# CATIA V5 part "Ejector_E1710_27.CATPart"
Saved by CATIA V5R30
Part number: Vyhazovac_7x160_4
Nomenclature: E1710/7x160
Description: MEUSBURGER
Property "Material": "1.221"
Publications: "__DrillHole", "Base"
Bounding box of the stored display mesh (mm): x -5.992 to 5.992, y -5.992 to 5.992, z 0 to 152
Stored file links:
  E:\Bakalarka\Model\Forma_v7\Ejector_E1710_27.CATPart
  E:\dev\MoldDesign\intel_a\startup\components\MoldCatalog\Ejector\Meusburger\Ejector_E1710\TableE1710.txt
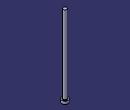
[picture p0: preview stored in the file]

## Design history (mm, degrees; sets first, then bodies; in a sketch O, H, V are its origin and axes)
Parameters
  Ref = "E1710/7x160" {design table}
  D1 = 7 mm {design table}
  D3 = 12 mm {design table}
  L = 160 mm {design table}
  L3 = 5 mm {design table}
  R = 0.5 mm {design table}
  k_d3 = 13 mm {design table}
  k_d1 = 7.2 mm {design table}
  k_F = 0.5 mm {design table}
  kl = 17 mm {design table}
  Mat = "1.221" {design table}
  HeatTreat = "ISO6751" {design table}
  Offset_Parting = 10 mm
  Anti_Rotation = "Normal"
  Anti_Rotation_D = 4 mm
  Anti_Rotation_D_Icut = 4 mm
  Add_Length_L = 1.3377 mm
  Add_Length_D3 = 0 mm
  SupplierRef = "Meusburger 2017"
  BmpRef = "F_MldEjectorD1"
  DrillHole_Length = 225 mm
  ValidationTest = false
  Anti_Rotation_D_min = 4 mm {= OffSet_D1 /2}
  Anti_Rotation_D_max = 5.925 mm {= D3/2-0.075mm}
  Anti_Rotation_D_ref = 4 mm {= Anti_Rotation_D}
  Anti_Rotation_D_Icut_ref = 4 mm {= Anti_Rotation_D_Icut}
  Anti_Rotation_Ref_Icut = 2.3246 mm
  Offset_L = 20 mm
  D = 7 mm {= D1}
  OffSet_D1 = 8 mm {= D1+2*R}
  OffSet_D3 = 13 mm {= D3+1mm}
  XG_Split = -45 mm
  YG_Split = -10 mm
  ZG_Split = -198 mm
  DirX_Split = 0 mm
  DirY_Split = 0 mm
  DirZ_Split = 1 mm
Set1 "BaseBody"
  Point1 "Base": (0, 0, 0)
  Plane1: type Offset, RefPlane xy-plane, Offset 225 {= DrillHole_Length}, reversed
  Sketch1 "Sketch.2" on xy-plane, origin (0, 0, 0), H (1, 0, 0), V (0, 1, 0)
    point P1 (-0.46, 1.1623)
    point P2 (0.46, 1.1623)
    construction line L1 (-0.46, 1.1623) -> (0.46, 1.1623)
    point P3 (0.46, -1.1623)
    line L2 (0.46, -1.1623) -> (0.46, 1.1623)
    point P4 (-0.46, -1.1623)
    construction line L3 (0.46, -1.1623) -> (-0.46, -1.1623)
    line L4 (-0.46, 1.1623) -> (-0.46, -1.1623)
    point P5 (-0.21, 1.1623)
    arc A1 centre (-0.21, 1.1623) radius 0.25 from (-0.21, 1.4123) to (-0.46, 1.1623) ccw
    point P7 (0.21, 1.1623)
    point P8 (0.21, 1.4123)
    arc A2 centre (0.21, 1.1623) radius 0.25 from (0.46, 1.1623) to (0.21, 1.4123) ccw
    line L5 (-0.21, 1.4123) -> (0.21, 1.4123)
    point P9 (-0.46, -1.1623)
    arc A3 centre (-0.21, -1.1623) radius 0.25 from (-0.46, -1.1623) to (-0.21, -1.4123) ccw
    point P11 (0.21, -1.4123)
    line L6 (-0.21, -1.4123) -> (0.21, -1.4123)
    point P12 (0.46, -1.1623)
    arc A4 centre (0.21, -1.1623) radius 0.25 from (0.21, -1.4123) to (0.46, -1.1623) ccw
    point P14 (-0.46, 1.1623)
    point P15 (-0.46, -1.1623)
    point P16 (0.46, 1.1623)
    point P17 (0.46, -1.1623)
    reference projected circle E1 centre (0, 0) radius 1.25 from edge [face of Shaft1 from Sketch2.L3 | face of Shaft1 from Sketch2.L4]
    reference projected circle E2 centre (0, 0) radius 1.25 from edge [face of Shaft1 from Sketch2.L3 | face of Shaft1 from Sketch2.L4]
    reference projected circle E3 centre (0, 0) radius 1.25 from edge [face of Shaft1 from Sketch2.L3 | face of Shaft1 from Sketch2.L4]
    reference projected circle E4 centre (0, 0) radius 1.25 from edge [face of Shaft1 from Sketch2.L3 | face of Shaft1 from Sketch2.L4]
    point P18 (-0.46, -1.1623)
    point P19 (-0.21, -1.4123)
    point P20 (0.21, -1.4123)
    point P21 (0.46, -1.1623)
    point P22 (-0.21, -1.4123)
    point P23 (0.21, -1.4123)
    distance P14 P15 = 2.3246 (reference)
    distance P16 P17 = 2.3246 (reference)
    distance L1 P14 = 0 (reference)
    radius A1 = 3.5
    distance L4 V = 4.01
    distance L2 V = 5.935
    distance L5 L6 = 12
    horizontal: L1 H, L3 H, L5 H
    vertical: L2 V, L4 V
    coincidence: P5 L1, P7 L1, P3 P12, P14 L4, P15 L4, P16 L2, P17 L2, P14 E1, P15 E2, P16 E3, P17 E4, P3 P21, P4 P18, P20 P23, P19 P22
    tangency: A1 L4, A2 L2, A2 L5, A1 L5
    symmetry: P1 P9 H, A1 A3 H, P8 P11 H, L5 L6 H, P2 P12 H, A2 A4 H
  DatumSurface1
Body1 "PartBody" (main body)
  Sketch2 "Sketch.1" on zx-plane, origin (0, 0, 0), H (-1, 0, 0), V (0, 0, 1)
    point P1 (0, 160)
    line L1 (3.5, 160) -> (0, 160)
    line L2 (3.5, 5) -> (3.5, 160)
    line L3 (6, 5) -> (3.5, 5)
    line L4 (6, 0) -> (6, 5)
    point P5 (0, 0)
    line L5 (0, 0) -> (6, 0)
    point P6 (0, 160)
    axis line L6 (0, 160) -> (0, 0)
    point P7 (0, 0)
    point P8 (3.5, 5)
    point P9 (3.5, 5)
    line L7 (0, 160) -> (0, 0)
    distance L5 L3 = 5 {= L3}
    distance L5 L1 = 160 {= L}
    distance L2 L6 = 3.5 {= D1 /2}
    distance L4 L6 = 6 {= D3 /2}
    coincidence: L6 P5, P1 L6, L5 H, L6 V, P7 O, P6 P1, P8 P9
    vertical: L2 V, L7 V
    horizontal: L1 H
  Shaft1 "Shaft.1": profile Sketch2, axis Sketch2.L6, angle 360
  Pocket1 "Pocket.1": profile Sketch1, direction (0, 0, 1), length 6, outer side, deactivated
  Pocket2 "Pocket.2": profile Sketch1, direction (0, 0, 1), length 6, outer side, deactivated
  Fillet1: radius 0.5 {= R}, on edge [face of Shaft1 from Sketch2.L2 | face of Shaft1 from Sketch2.L3]
  Pocket3: profile face of Shaft1 from Sketch2.L1, direction along face of Shaft1 from Sketch2.L1 reversed, up to face of DatumSurface1
Body2 "__DrillHole"
  Sketch3 "Sketch.3" on face of Shaft1, origin (0, 0, 0), H (1, 0, 0), V (0, -1, 0)
    point P1 (0, 0)
    reference projected point E1 (0, 0) from Point1
    coincidence: E1 P1
  Hole1 "Hole.1": placed by Sketch3, at (0, 0, 0) direction (0, 0, 1), diameter 8 {= OffSet_D1}, depth 140 {= L-Offset_L}
  Sketch4 "Sketch.4" on face of Shaft1, origin (0, 0, 0), H (1, 0, 0), V (0, -1, 0)
    point P1 (0, 0)
    reference projected point E1 (0, 0) from Point1
    coincidence: E1 P1
  Hole2 "Hole.2": placed by Sketch4, at (0, 0, 0) direction (0, 0, 1), diameter 7 {= D1}, depth 160 {= L}
  Sketch5 "Sketch.5" on face of Shaft1 from Sketch2.L3, origin (0, 0, 5), H (1, 0, 0), V (0, 1, 0)
    point P1 (0, 0)
    reference projected point E1 (0, 0) from Point1
    coincidence: E1 P1
  Hole3 "Hole.3": placed by Sketch5, at (0, 0, 5) direction (0, 0, -1), diameter 13 {= OffSet_D3}, depth 230 {= L3 +DrillHole_Length}
  Chamfer1: length 0.5 {= k_F}, angle 45, on edge [face of Hole1 | face of Hole3]
  Body3 "__Body.1"
    Pocket4 "Pocket.3": profile Sketch1, direction (0, 0, -1), length 225, opposite side length 5, deactivated
  Assemble1: tool Body3
  Chamfer2: length 0.5 {= k_F}, angle 45, on edge [start face of Pocket4 | face of Hole1], deactivated
  Body4 "__Body.2"
    Pocket5 "Pocket.4": profile Sketch1, direction (0, 0, -1), length 225, opposite side length 5, deactivated
  Assemble2: tool Body4
  Chamfer3: length 0.5 {= k_F}, angle 45, on edge [start face of Pocket5 | face of Hole1], deactivated
Relations
  design table "TableE1710", configuration 278, drives Ref, D1, D3, L, L3, R, k_d3, k_d1, k_F, kl, Mat, HeatTreat
  Offset_L = 20mm (deactivated)
  rule "Cut_Head_rule":
    let sketch_cut (length)
    let PartBody_Pocket_Sketch (Boolean)
    let I_PartBody_Pocket (Boolean)
    let D_PartBody_Pocket (Boolean)
    let N_DrillHole_Hole (Boolean)
    let N_DrillHole_Hole_Sketch (Boolean)
    let I_DrillHole_Pocket (Boolean)
    let D_DrillHole_Pocket (Boolean)
    /* --------------------------------------------------------------------------------------*/
    if Anti_Rotation =="Normal"
    {
    	sketch_cut=Anti_Rotation_D_max
    	PartBody_Pocket_Sketch = false
    	I_PartBody_Pocket = false
    	D_PartBody_Pocket = false
    	N_DrillHole_Hole = true
    	N_DrillHole_Hole_Sketch = true
    	I_DrillHole_Pocket = false
    	D_DrillHole_Pocket = false
    	Chamfer1.Activity= true
    	Chamfer2.Activity= false
    	Chamfer3.Activity= false
    }
    if Anti_Rotation == "I_Cut"
    {
    	sketch_cut=Anti_Rotation_D_Icut_ref
    	PartBody_Pocket_Sketch = true
    	I_PartBody_Pocket = true
    	D_PartBody_Pocket = false
    	N_DrillHole_Hole = false
    	N_DrillHole_Hole_Sketch = false
    	I_DrillHole_Pocket = true
    	D_DrillHole_Pocket = false
    	Chamfer1.Activity= false
    	Chamfer2.Activity= true
    	Chamfer3.Activity= false
    }
    if Anti_Rotation =="D_Cut"
    {
    	sketch_cut=Anti_Rotation_D_max
    	PartBody_Pocket_Sketch = true
    	I_PartBody_Pocket = false
    	D_PartBody_Pocket = true
    	N_DrillHole_Hole = false
    	N_DrillHole_Hole_Sketch = false
    	I_DrillHole_Pocket = false
    	D_DrillHole_Pocket = true
    	Chamfer1.Activity= false
    	Chamfer2.Activity= false
    	Chamfer3.Activity= true
    }
    /* --------------------------------------------------------------------------------------*/
    Sketch1.distance(L2 V) = sketch_cut+0.01mm
    Sketch1.distance(L4 V) =Anti_Rotation_D_ref+0.01mm
    Sketch1.radius(A1) =D/2
    Pocket4.FirstLimit.Depth = DrillHole_Length
    Pocket5.FirstLimit.Depth = DrillHole_Length
    Pocket1.FirstLimit.Depth = L3+1mm
    Pocket2.FirstLimit.Depth = L3+1mm
    Pocket4.SecondLimit.Depth = L3
    Pocket5.SecondLimit.Depth =L3
    Pocket1.Activity = I_PartBody_Pocket
    Pocket2.Activity = D_PartBody_Pocket
    Sketch1.Activity =PartBody_Pocket_Sketch
    Hole3.Activity= N_DrillHole_Hole
    Sketch5.Activity = N_DrillHole_Hole_Sketch
    Pocket4.Activity = I_DrillHole_Pocket
    Pocket5.Activity  = D_DrillHole_Pocket
  rule "Anti_Rotation_Icut_constrain":
    let Ref1(length)
    let Ref2(length)
    let Ref3(length)
    let Diam1(length)
    let Diam2(length)
    let Add_Length_Lmin (length)
    Ref1=Sketch1.distance(P14 P15)
    Ref2=Sketch1.distance(P16 P17)
    Diam1=D
    Diam2=D3
    /* --------------------------------------------------------------------*/
    if Ref1 >Ref2
    	Anti_Rotation_Ref_Icut = Ref1
    else
    	Anti_Rotation_Ref_Icut  =Ref2
    Add_Length_D3 .InferiorRange=Anti_Rotation_Ref_Icut /2+Diam1/2 -Diam2/2
    if Add_Length_D3 .InferiorRange<0mm
    	Add_Length_D3 .InferiorRange=0mm
    if ValidationTest == "true"
    	Ref3   = 2*Add_Length_L +Anti_Rotation_Ref_Icut  +2*Diam1/2
    else
    	Ref3  =Diam2+2*Add_Length_D3
    if Ref3 <Diam2
    {
    	Ref3 =Diam2
    }
    /* --------------------------------------------------------------------*/
    Sketch1.distance(L5 L6) = Ref3
    Add_Length_L .InferiorRange=Diam2/2-Anti_Rotation_Ref_Icut/2-Diam1/2
    Add_Length_Lmin=Diam2/2-Anti_Rotation_Ref_Icut/2-Diam1/2
    if Add_Length_Lmin<0mm
    	Add_Length_L .InferiorRange=0mm
    else
    	Add_Length_L .InferiorRange=Add_Length_Lmin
